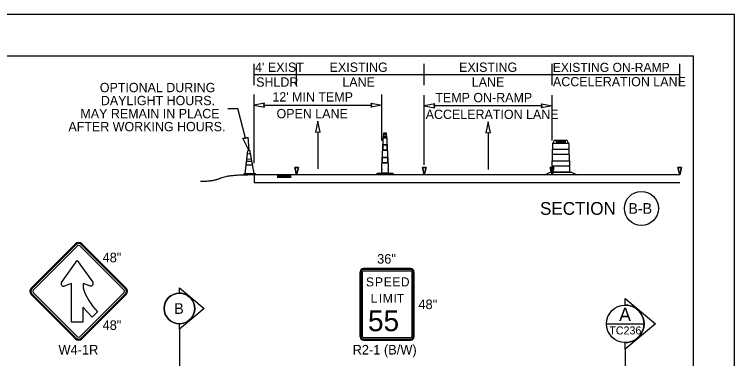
# Model space of a CAD drawing. Extents: x 99999 to 100116, y 99995 to 100013.
# Drawn here: x 100050.65 to 100056.06, y 100008.1 to 100010.69 of the extents above; entities that cross this region are included whole.
import ezdxf

# ---------------------------------------------------------------- set-up
doc = ezdxf.new("R2010")
doc.units = 0
for name, color, linetype in [('SH_GI_PlotLimits', 7, 'Continuous'), ('SH_GI_SectionCut', 7, 'Continuous'), ('SH_GI_SheetBorder', 7, 'Continuous'), ('SH_TI_WZSectionCut', 7, 'Continuous'), ('TR_SN_ConstructionSigns', 7, 'Continuous'), ('TR_WZ_ArrowLeftStrRightTurn', 7, 'Continuous'), ('TR_WZ_TallChanDeviceElev', 7, 'Continuous'), ('TR_WZ_TrafficConeElev', 7, 'Continuous'), ('TR_WZ_TrafficSafetyDrumElev', 7, 'Continuous'), ('TR_WZ_WorkZoneDetails', 7, 'Continuous'), ('TR_WZ_WorkZoneTextCurrent', 7, 'Continuous')]:
    doc.layers.add(name, color=color, linetype=linetype)

msp = doc.modelspace()

# ---------------------------------------------------------------- linework, layer by layer
at = {"layer": 'SH_GI_PlotLimits'}
msp.add_lwpolyline([(100039.0625, 99999.6875), (100056.0625, 99999.6875), (100056.0625, 100010.6875), (100039.0625, 100010.6875)], close=True, dxfattribs=at)
at = {"layer": 'SH_GI_SectionCut'}
for p, q in [((100051.8894, 100008.589), (100051.8894, 100008.6297)), ((100051.8894, 100008.6297), (100052.0755, 100008.4738)), ((100052.0755, 100008.4738), (100051.8894, 100008.3179)), ((100051.8894, 100008.3179), (100051.8894, 100008.3586)), ((100051.8894, 100008.3179), (100051.8894, 100006.8828))]:
    msp.add_line(p, q, dxfattribs=at)
msp.add_circle((100051.8894, 100008.4738), 0.1152, dxfattribs=at)
msp.add_circle((100051.8894, 100008.4738), 0.1152, dxfattribs=at)
for start, end in [(90.0022, 269.9978), (269.9978, 90.0022), (269.9978, 90.0022)]:
    msp.add_arc((100051.8894, 100008.4738), 0.1152, start, end, dxfattribs=at)
at = {"layer": 'SH_GI_SheetBorder'}
for p, q in [((100040, 100010.375), (100055.75, 100010.375)), ((100055.75, 100010.375), (100055.75, 100000))]:
    msp.add_line(p, q, dxfattribs=at)
at = {"layer": 'SH_TI_WZSectionCut'}
for p, q in [((100052.45, 100009.5666), (100052.45, 100010.0836)), ((100053.41, 100009.7388), (100053.41, 100010.0836)), ((100052.525, 100010.0036), (100053.335, 100010.0036)), ((100055.2407, 100008.4993), (100055.2407, 100008.5492)), ((100055.2407, 100008.5492), (100055.4688, 100008.358)), ((100055.4688, 100008.358), (100055.2407, 100008.1669)), ((100055.2407, 100008.1669), (100055.2407, 100008.2168)), ((100055.2407, 100008.1669), (100055.2407, 100006.4389))]:
    msp.add_line(p, q, dxfattribs=at)
for points in [[(100052.45, 100010.0036), (100052.5286, 100009.9882), (100052.525, 100010.0036), (100052.5286, 100010.019)], [(100053.41, 100010.0036), (100053.3314, 100009.9882), (100053.335, 100010.0036), (100053.3314, 100010.019)]]:
    msp.add_lwpolyline(points, close=True, dxfattribs=at)
msp.add_lwpolyline([(100055.0995, 100008.3581), (100055.3819, 100008.3581)], dxfattribs=at)
msp.add_circle((100055.2407, 100008.358), 0.1412, dxfattribs=at)
msp.add_arc((100055.2407, 100008.358), 0.1412, 269.9978, 90.0022, dxfattribs=at)
at = {"layer": 'TR_SN_ConstructionSigns'}
for p, q in [((100051.1081, 100008.9607), (100050.774, 100008.6266)), ((100051.1141, 100008.9548), (100050.78, 100008.6207)), ((100050.7899, 100008.6107), (100051.124, 100008.9448)), ((100051.1399, 100008.9448), (100051.4741, 100008.6107)), ((100051.484, 100008.6207), (100051.1499, 100008.9548)), ((100051.49, 100008.6266), (100051.1559, 100008.9607)), ((100051.0032, 100008.669), (100051.121, 100008.8347)), ((100051.121, 100008.8347), (100051.2375, 100008.6708)), ((100053.2728, 100008.7749), (100053.6272, 100008.7749)), ((100053.6272, 100008.7749), (100053.2728, 100008.7749)), ((100053.2475, 100008.2602), (100053.2475, 100008.7496)), ((100053.2475, 100008.7496), (100053.2475, 100008.2602)), ((100053.2546, 100008.7496), (100053.2546, 100008.2602)), ((100053.2644, 100008.2602), (100053.2644, 100008.7496)), ((100053.6272, 100008.7679), (100053.2728, 100008.7679)), ((100053.2728, 100008.758), (100053.6272, 100008.758)), ((100053.6357, 100008.7496), (100053.6357, 100008.2602)), ((100053.6455, 100008.2602), (100053.6455, 100008.7496)), ((100053.6525, 100008.7496), (100053.6525, 100008.2602)), ((100053.6525, 100008.2602), (100053.6525, 100008.7496)), ((100051.0784, 100008.6609), (100051.0235, 100008.6419)), ((100051.0784, 100008.3708), (100051.0784, 100008.6609)), ((100051.2171, 100008.6438), (100051.1652, 100008.6624)), ((100051.1652, 100008.6624), (100051.1652, 100008.63)), ((100050.774, 100008.5789), (100051.1081, 100008.2448)), ((100050.78, 100008.5849), (100051.1141, 100008.2508)), ((100051.124, 100008.2607), (100050.7899, 100008.5948)), ((100051.4741, 100008.5948), (100051.1399, 100008.2607)), ((100051.1499, 100008.2508), (100051.484, 100008.5849)), ((100051.1559, 100008.2448), (100051.49, 100008.5789)), ((100051.2329, 100008.4077), (100051.1637, 100008.4842)), ((100051.1637, 100008.4842), (100051.1637, 100008.3708)), ((100051.2741, 100008.4489), (100051.2329, 100008.4077)), ((100051.1637, 100008.3708), (100051.0784, 100008.3708)), ((100053.6272, 100008.2518), (100053.2728, 100008.2518)), ((100053.2728, 100008.2419), (100053.6272, 100008.2419)), ((100053.6272, 100008.2349), (100053.2728, 100008.2349)), ((100053.2728, 100008.2349), (100053.6272, 100008.2349))]:
    msp.add_line(p, q, dxfattribs=at)
for centre, radius, start, end in [((100051.132, 100008.9369), 0.0338, 45, 135), ((100051.132, 100008.9369), 0.0253, 45, 135), ((100051.132, 100008.9369), 0.0113, 45, 135), ((100053.2728, 100008.7496), 0.0253, 90, 180), ((100053.2728, 100008.7496), 0.0253, 90, 180), ((100053.6272, 100008.7496), 0.0253, 360, 90), ((100053.6272, 100008.7496), 0.0253, 360, 90), ((100053.2728, 100008.7496), 0.0183, 90, 180), ((100053.2728, 100008.7496), 0.00844, 90, 180), ((100053.6272, 100008.7496), 0.0183, 0, 90), ((100053.6272, 100008.7496), 0.00844, 360, 90), ((100051.0177, 100008.6587), 0.0177, 144.5862, 289.1062), ((100051.2231, 100008.6606), 0.0177, 250.3331, 35.4138), ((100050.7979, 100008.6028), 0.0338, 135, 225), ((100050.7979, 100008.6028), 0.0253, 135, 225), ((100050.7979, 100008.6028), 0.0113, 135, 225), ((100051.5783, 100008.7551), 0.4316, 196.843, 225.185), ((100051.4661, 100008.6028), 0.0113, 315, 45), ((100051.4661, 100008.6028), 0.0253, 315, 45), ((100051.4661, 100008.6028), 0.0338, 315, 45), ((100051.132, 100008.2687), 0.0338, 225, 315), ((100051.132, 100008.2687), 0.0253, 225, 315), ((100051.132, 100008.2687), 0.0113, 225, 315), ((100053.2728, 100008.2602), 0.0253, 180, 270), ((100053.2728, 100008.2602), 0.0253, 180, 270), ((100053.2728, 100008.2602), 0.0183, 180, 270), ((100053.2728, 100008.2602), 0.00844, 180, 270), ((100053.6272, 100008.2602), 0.0253, 270, 360), ((100053.6272, 100008.2602), 0.0183, 270, 360), ((100053.6272, 100008.2602), 0.00844, 270, 0), ((100053.6272, 100008.2602), 0.0253, 270, 360)]:
    msp.add_arc(centre, radius, start, end, dxfattribs=at)
at = {"layer": 'TR_WZ_ArrowLeftStrRightTurn'}
for p, q in [((100052.93, 100009.8039), (100052.93, 100009.524)), ((100054.21, 100009.7986), (100054.21, 100009.5187))]:
    msp.add_line(p, q, dxfattribs=at)
for points in [[(100052.93, 100009.884), (100052.9135, 100009.8), (100052.93, 100009.8039), (100052.9465, 100009.8)], [(100054.21, 100009.8787), (100054.1935, 100009.7947), (100054.21, 100009.7986), (100054.2265, 100009.7947)]]:
    msp.add_lwpolyline(points, close=True, dxfattribs=at)
at = {"layer": 'TR_WZ_TallChanDeviceElev'}
for p, q in [((100053.4494, 100009.7588), (100053.42, 100009.7588)), ((100053.42, 100009.7588), (100053.4494, 100009.7588)), ((100053.42, 100009.7588), (100053.4494, 100009.7588)), ((100053.4422, 100009.7848), (100053.4266, 100009.7848)), ((100053.4266, 100009.767), (100053.4422, 100009.767)), ((100053.4178, 100009.7051), (100053.4515, 100009.7051)), ((100053.4178, 100009.6655), (100053.4178, 100009.7051)), ((100053.4515, 100009.7051), (100053.4515, 100009.6655)), ((100053.4515, 100009.6655), (100053.4178, 100009.6655)), ((100053.4139, 100009.5707), (100053.4139, 100009.6103)), ((100053.4139, 100009.6103), (100053.4555, 100009.6103)), ((100053.4555, 100009.6103), (100053.4555, 100009.5707)), ((100053.4555, 100009.5707), (100053.4139, 100009.5707)), ((100053.3747, 100009.4788), (100053.3747, 100009.492)), ((100053.4947, 100009.4788), (100053.3747, 100009.4788)), ((100053.4947, 100009.492), (100053.4947, 100009.4788))]:
    msp.add_line(p, q, dxfattribs=at)
for points in [[(100053.4198, 100009.7106), (100053.4198, 100009.7555)], [(100053.4198, 100009.7106), (100053.4198, 100009.7555)], [(100053.4496, 100009.7555), (100053.4496, 100009.7106)], [(100053.4496, 100009.7555), (100053.4496, 100009.7106)], [(100053.4178, 100009.6632), (100053.4178, 100009.7074)], [(100053.4178, 100009.6632), (100053.4178, 100009.7074)], [(100053.4515, 100009.7074), (100053.4515, 100009.6632)], [(100053.4515, 100009.7074), (100053.4515, 100009.6632)], [(100053.4159, 100009.6158), (100053.4159, 100009.66)], [(100053.4159, 100009.6158), (100053.4159, 100009.66)], [(100053.4535, 100009.66), (100053.4535, 100009.6158)], [(100053.4535, 100009.66), (100053.4535, 100009.6158)], [(100053.4139, 100009.5685), (100053.4139, 100009.6125)], [(100053.4139, 100009.5685), (100053.4139, 100009.6125)], [(100053.4555, 100009.6125), (100053.4555, 100009.5685)], [(100053.4555, 100009.6125), (100053.4555, 100009.5685)], [(100053.412, 100009.5212), (100053.412, 100009.5653)], [(100053.412, 100009.5212), (100053.412, 100009.5653)], [(100053.4574, 100009.5653), (100053.4574, 100009.5212)], [(100053.4574, 100009.5653), (100053.4574, 100009.5212)], [(100053.3747, 100009.492), (100053.41, 100009.492), (100053.4594, 100009.492), (100053.4947, 100009.492)], [(100053.4594, 100009.492), (100053.41, 100009.492), (100053.41, 100009.518)], [(100053.4594, 100009.492), (100053.41, 100009.492), (100053.41, 100009.518)], [(100053.4594, 100009.518), (100053.4594, 100009.492)], [(100053.4594, 100009.518), (100053.4594, 100009.492)]]:
    msp.add_lwpolyline(points, dxfattribs=at)
for points in [[(100053.4494, 100009.7588), (100053.4467, 100009.793), (100053.4225, 100009.793), (100053.42, 100009.7588)], [(100053.4515, 100009.7051), (100053.4178, 100009.7051), (100053.4178, 100009.6655), (100053.4515, 100009.6655)], [(100053.4555, 100009.6103), (100053.4139, 100009.6103), (100053.4139, 100009.5707), (100053.4555, 100009.5707)]]:
    msp.add_lwpolyline(points, close=True, dxfattribs=at)
for centre, major_axis, ratio, start_param, end_param in [((100053.42, 100009.7548), (0, 0.00412), 0.059356, 0.177149, 1.393647), ((100053.42, 100009.7548), (0, 0.00412), 0.059356, 0.177149, 1.393647), ((100053.4266, 100009.7759), (0, 0.00891), 0.07945, 0, 3.141593), ((100053.4422, 100009.7759), (0, 0.00891), 0.07945, 3.141593, 6.283185), ((100053.4493, 100009.7548), (0, 0.00412), 0.059356, 4.889538, 6.106036), ((100053.4493, 100009.7548), (0, 0.00412), 0.059356, 4.889538, 6.106036), ((100053.4214, 100009.7047), (0, 0.00651), 0.609371, 0.4288, 1.141997), ((100053.4214, 100009.7047), (0, 0.00651), 0.609371, 0.4288, 1.141997), ((100053.4479, 100009.7047), (0, 0.00651), 0.609371, 5.141189, 5.854386), ((100053.4479, 100009.7047), (0, 0.00651), 0.609371, 5.141189, 5.854386), ((100053.4195, 100009.6573), (0, 0.00651), 0.609371, 0.4288, 1.141997), ((100053.4195, 100009.6573), (0, 0.00651), 0.609371, 0.4288, 1.141997), ((100053.4499, 100009.6573), (0, 0.00651), 0.609371, 5.141189, 5.854386), ((100053.4499, 100009.6573), (0, 0.00651), 0.609371, 5.141189, 5.854386), ((100053.4175, 100009.6098), (0, 0.00651), 0.609371, 0.4288, 1.141997), ((100053.4175, 100009.6098), (0, 0.00651), 0.609371, 0.4288, 1.141997), ((100053.4519, 100009.6098), (0, 0.00651), 0.609371, 5.141189, 5.854386), ((100053.4519, 100009.6098), (0, 0.00651), 0.609371, 5.141189, 5.854386), ((100053.4156, 100009.5625), (0, 0.00651), 0.609371, 0.4288, 1.141997), ((100053.4156, 100009.5625), (0, 0.00651), 0.609371, 0.4288, 1.141997), ((100053.4538, 100009.5625), (0, 0.00651), 0.609371, 5.141189, 5.854386), ((100053.4538, 100009.5625), (0, 0.00651), 0.609371, 5.141189, 5.854386), ((100053.4136, 100009.5153), (0, 0.00651), 0.609371, 0.4288, 1.141997), ((100053.4136, 100009.5153), (0, 0.00651), 0.609371, 0.4288, 1.141997), ((100053.4558, 100009.5153), (0, 0.00651), 0.609371, 5.141189, 5.854386), ((100053.4558, 100009.5153), (0, 0.00651), 0.609371, 5.141189, 5.854386)]:
    msp.add_ellipse(centre, major_axis=major_axis, ratio=ratio, start_param=start_param, end_param=end_param, dxfattribs=at)
at = {"layer": 'TR_WZ_TrafficConeElev'}
for p, q in [((100052.3959, 100009.5953), (100052.4011, 100009.6388)), ((100052.4011, 100009.6388), (100052.4213, 100009.6395)), ((100052.4213, 100009.6395), (100052.4294, 100009.5964)), ((100052.3908, 100009.5518), (100052.3944, 100009.5819)), ((100052.3944, 100009.5819), (100052.4319, 100009.5832)), ((100052.4294, 100009.5964), (100052.3959, 100009.5953)), ((100052.4319, 100009.5832), (100052.4375, 100009.5534)), ((100052.4375, 100009.5534), (100052.3908, 100009.5518)), ((100052.3702, 100009.4827), (100052.3735, 100009.4861)), ((100052.3705, 100009.476), (100052.3702, 100009.4827)), ((100052.4629, 100009.4792), (100052.3705, 100009.476)), ((100052.4497, 100009.4887), (100052.4592, 100009.4891)), ((100052.4592, 100009.4891), (100052.4627, 100009.4858)), ((100052.4627, 100009.4858), (100052.4629, 100009.4792))]:
    msp.add_line(p, q, dxfattribs=at)
msp.add_lwpolyline([(100052.4497, 100009.4887), (100052.383, 100009.4865), (100052.4041, 100009.664), (100052.4166, 100009.6644)], close=True, dxfattribs=at)
msp.add_lwpolyline([(100052.4497, 100009.4887), (100052.383, 100009.4865), (100052.4041, 100009.664), (100052.4166, 100009.6644)], close=True, dxfattribs=at)
msp.add_lwpolyline([(100052.3735, 100009.4861), (100052.383, 100009.4865), (100052.4497, 100009.4887)], dxfattribs=at)
at = {"layer": 'TR_WZ_TrafficSafetyDrumElev'}
for p, q in [((100054.6967, 100009.7188), (100054.8151, 100009.7188)), ((100054.6967, 100009.7188), (100054.8151, 100009.7188)), ((100054.7243, 100009.734), (100054.7897, 100009.734)), ((100054.7897, 100009.7236), (100054.7243, 100009.7236)), ((100054.6944, 100009.6724), (100054.8174, 100009.6724)), ((100054.6944, 100009.6325), (100054.6944, 100009.6724)), ((100054.8174, 100009.6724), (100054.8174, 100009.6325)), ((100054.6915, 100009.5844), (100054.8203, 100009.5844)), ((100054.6915, 100009.5445), (100054.6915, 100009.5844)), ((100054.8174, 100009.6325), (100054.6944, 100009.6325)), ((100054.8203, 100009.5844), (100054.8203, 100009.5445)), ((100054.8203, 100009.5445), (100054.6915, 100009.5445))]:
    msp.add_line(p, q, dxfattribs=at)
for points in [[(100054.6959, 100009.676), (100054.6959, 100009.7172)], [(100054.6959, 100009.676), (100054.6959, 100009.7172)], [(100054.8159, 100009.7172), (100054.8159, 100009.676)], [(100054.8159, 100009.7172), (100054.8159, 100009.676)], [(100054.6944, 100009.632), (100054.6944, 100009.673)], [(100054.6944, 100009.632), (100054.6944, 100009.673)], [(100054.8174, 100009.673), (100054.8174, 100009.632)], [(100054.8174, 100009.673), (100054.8174, 100009.632)], [(100054.6915, 100009.5439), (100054.6915, 100009.5849)], [(100054.6915, 100009.5439), (100054.6915, 100009.5849)], [(100054.693, 100009.5879), (100054.693, 100009.629)], [(100054.693, 100009.5879), (100054.693, 100009.629)], [(100054.8189, 100009.629), (100054.8189, 100009.5879)], [(100054.8189, 100009.629), (100054.8189, 100009.5879)], [(100054.8203, 100009.5849), (100054.8203, 100009.5439)], [(100054.8203, 100009.5849), (100054.8203, 100009.5439)], [(100054.8218, 100009.5409), (100054.8218, 100009.4988), (100054.69, 100009.4988), (100054.69, 100009.5409)], [(100054.8218, 100009.5409), (100054.8218, 100009.4988), (100054.69, 100009.4988), (100054.69, 100009.5409)]]:
    msp.add_lwpolyline(points, dxfattribs=at)
for points in [[(100054.8151, 100009.7188), (100054.8046, 100009.7388), (100054.7072, 100009.7388), (100054.6967, 100009.7188)], [(100054.6359, 100009.4788), (100054.6761, 100009.4988), (100054.8357, 100009.4988), (100054.8759, 100009.4788)]]:
    msp.add_lwpolyline(points, close=True, dxfattribs=at)
for centre, major_axis, ratio, start_param, end_param in [((100054.6969, 100009.7168), (0, 0.00199), 0.493438, 0.177149, 1.393647), ((100054.6969, 100009.7168), (0, 0.00199), 0.493438, 0.177149, 1.393647), ((100054.7243, 100009.7288), (0, 0.0052), 0.570305, 0, 3.141593), ((100054.7897, 100009.7288), (0, 0.0052), 0.570305, 3.141593, 6.283185), ((100054.8149, 100009.7168), (0, 0.00199), 0.493438, 4.889538, 6.106036), ((100054.8149, 100009.7168), (0, 0.00199), 0.493438, 4.889538, 6.106036), ((100054.6972, 100009.6705), (0, 0.00606), 0.493438, 0.4288, 1.141997), ((100054.6972, 100009.6705), (0, 0.00606), 0.493438, 0.4288, 1.141997), ((100054.8147, 100009.6705), (0, 0.00606), 0.493438, 5.141189, 5.854386), ((100054.8147, 100009.6705), (0, 0.00606), 0.493438, 5.141189, 5.854386), ((100054.6942, 100009.5824), (0, 0.00606), 0.493438, 0.4288, 1.141997), ((100054.6942, 100009.5824), (0, 0.00606), 0.493438, 0.4288, 1.141997), ((100054.6957, 100009.6265), (0, 0.00606), 0.493438, 0.4288, 1.141997), ((100054.6957, 100009.6265), (0, 0.00606), 0.493438, 0.4288, 1.141997), ((100054.8161, 100009.6265), (0, 0.00606), 0.493438, 5.141189, 5.854386), ((100054.8161, 100009.6265), (0, 0.00606), 0.493438, 5.141189, 5.854386), ((100054.8176, 100009.5824), (0, 0.00606), 0.493438, 5.141189, 5.854386), ((100054.8176, 100009.5824), (0, 0.00606), 0.493438, 5.141189, 5.854386), ((100054.6927, 100009.5384), (0, 0.00606), 0.493438, 0.4288, 1.141997), ((100054.6927, 100009.5384), (0, 0.00606), 0.493438, 0.4288, 1.141997), ((100054.8191, 100009.5384), (0, 0.00606), 0.493438, 5.141189, 5.854386), ((100054.8191, 100009.5384), (0, 0.00606), 0.493438, 5.141189, 5.854386)]:
    msp.add_ellipse(centre, major_axis=major_axis, ratio=ratio, start_param=start_param, end_param=end_param, dxfattribs=at)
at = {"layer": 'TR_WZ_WorkZoneDetails'}
for p, q in [((100052.45, 100010.154), (100052.45, 100010.314)), ((100052.77, 100010.154), (100052.77, 100010.314)), ((100053.73, 100010.154), (100053.73, 100010.314)), ((100054.69, 100010.154), (100054.69, 100010.314)), ((100055.65, 100010.154), (100055.65, 100010.314)), ((100052.45, 100010.234), (100052.77, 100010.234)), ((100052.77, 100010.234), (100053.73, 100010.234)), ((100053.73, 100010.234), (100054.69, 100010.234)), ((100054.69, 100010.234), (100055.65, 100010.234)), ((100053.73, 100009.5546), (100053.73, 100010.0783)), ((100054.69, 100009.7388), (100054.69, 100010.0783)), ((100052.2522, 100009.9799), (100052.3284, 100009.9799)), ((100052.3868, 100009.7549), (100052.3284, 100009.9799)), ((100054.615, 100009.9983), (100053.805, 100009.9983)), ((100055.65, 100009.4787), (100052.45, 100009.4787)), ((100052.45, 100009.4787), (100052.45, 100009.4187)), ((100052.6236, 100009.4746), (100052.73, 100009.4746)), ((100052.6236, 100009.4701), (100052.73, 100009.4701)), ((100052.6236, 100009.4655), (100052.73, 100009.4655)), ((100052.6236, 100009.4614), (100052.73, 100009.4614)), ((100055.65, 100009.4187), (100052.45, 100009.4187))]:
    msp.add_line(p, q, dxfattribs=at)
for points in [[(100053.73, 100009.9983), (100053.8086, 100009.9829), (100053.805, 100009.9983), (100053.8086, 100010.0137)], [(100054.69, 100009.9983), (100054.6114, 100009.9829), (100054.615, 100009.9983), (100054.6114, 100010.0137)], [(100052.4103, 100009.6642), (100052.367, 100009.7545), (100052.3868, 100009.7549), (100052.4044, 100009.7641)], [(100052.77, 100009.4787), (100052.7566, 100009.5346), (100052.7833, 100009.5346)], [(100053.73, 100009.4787), (100053.7166, 100009.5346), (100053.7433, 100009.5346)], [(100054.69, 100009.4787), (100054.6766, 100009.5346), (100054.7033, 100009.5346)], [(100055.65, 100009.4787), (100055.6366, 100009.5346), (100055.6633, 100009.5346)]]:
    msp.add_lwpolyline(points, close=True, dxfattribs=at)
for points in [[(100052.7833, 100009.5346), (100052.7566, 100009.5346), (100052.77, 100009.4787), (100052.7833, 100009.5346)], [(100053.7433, 100009.5346), (100053.7166, 100009.5346), (100053.73, 100009.4787), (100053.7433, 100009.5346)], [(100054.7033, 100009.5346), (100054.6766, 100009.5346), (100054.69, 100009.4787), (100054.7033, 100009.5346)], [(100055.6633, 100009.5346), (100055.6366, 100009.5346), (100055.65, 100009.4787), (100055.6633, 100009.5346)]]:
    msp.add_lwpolyline(points, dxfattribs=at)
msp.add_circle((100055.3621, 100009.2268), 0.128, dxfattribs=at)
msp.add_open_spline([(100052.45, 100009.4787), (100052.2491, 100009.4787), (100052.1487, 100009.429), (100052.0483, 100009.429)], degree=2, dxfattribs=at)

# ---------------------------------------------------------------- texts
at = {"layer": 'SH_GI_SectionCut'}
msp.add_text('B', height=0.08, rotation=0.01, dxfattribs=at).set_placement((100051.8507, 100008.4331))
at = {"layer": 'SH_TI_WZSectionCut'}
for s, height, rotation, p in [('A', 0.1, 0.01, (100055.1945, 100008.3787)), ('TC236', 0.06, 360, (100055.1209, 100008.2781))]:
    msp.add_text(s, height=height, rotation=rotation, dxfattribs=at).set_placement(p)
at = {"layer": 'TR_SN_ConstructionSigns'}
for s, height, p in [('48"', 0.072, (100051.3118, 100008.8213)), ('36"', 0.072, (100053.3753, 100008.8109)), ('S', 0.0675, (100053.2914, 100008.6399)), ('P', 0.0675, (100053.3596, 100008.6399)), ('E', 0.0675, (100053.4257, 100008.6399)), ('E', 0.0675, (100053.4899, 100008.6399)), ('D', 0.0675, (100053.554, 100008.6399)), ('L', 0.0675, (100053.3265, 100008.5162)), ('I', 0.0675, (100053.3886, 100008.5162)), ('M', 0.0675, (100053.4183, 100008.5162)), ('I', 0.0675, (100053.4993, 100008.5162)), ('T', 0.0675, (100053.5229, 100008.5162)), ('48"', 0.072, (100053.6858, 100008.4689)), ('55', 0.1575, (100053.3068, 100008.3024)), ('48"', 0.072, (100051.3118, 100008.3122)), ('W4-1R', 0.072, (100050.9805, 100008.1269)), ('R2-1 (B/W)', 0.072, (100053.1913, 100008.1269))]:
    msp.add_text(s, height=height, rotation=360, dxfattribs=at).set_placement(p)
at = {"layer": 'TR_WZ_WorkZoneDetails'}
for s, height, p in [("4' EXIST", 0.07, (100052.4583, 100010.255)), ('EXISTING', 0.07, (100053.0185, 100010.255)), ('EXISTING', 0.07, (100053.9912, 100010.255)), ('EXISTING ON-RAMP', 0.068, (100054.6955, 100010.2547)), ('SHLDR', 0.07, (100052.4663, 100010.143)), ('LANE', 0.07, (100053.1142, 100010.143)), ('LANE', 0.07, (100054.0869, 100010.143)), ('ACCELERATION LANE', 0.07, (100054.6973, 100010.1463)), ("12' MIN TEMP", 0.07, (100052.5882, 100010.0316)), ('TEMP ON-RAMP', 0.07, (100053.8129, 100010.0263)), ('OPEN LANE', 0.07, (100052.6194, 100009.9056)), ('ACCELERATION LANE', 0.07, (100053.7405, 100009.9003))]:
    msp.add_text(s, height=height, dxfattribs=at).set_placement(p)
for s, height, p in [('SECTION', 0.096, (100054.5996, 100009.1788)), ('B-B', 0.08, (100055.264, 100009.1868))]:
    msp.add_text(s, height=height, rotation=360, dxfattribs=at).set_placement(p)
at = {"layer": 'TR_WZ_WorkZoneTextCurrent'}
for s, p in [('OPTIONAL DURING', (100051.291, 100010.1019)), ('DAYLIGHT HOURS.', (100051.2989, 100010.0039)), ('MAY REMAIN IN PLACE', (100051.1453, 100009.9059)), ('AFTER WORKING HOURS.', (100051.0552, 100009.8079))]:
    msp.add_text(s, height=0.07, dxfattribs=at).set_placement(p)

doc.saveas('drawing.dxf')
